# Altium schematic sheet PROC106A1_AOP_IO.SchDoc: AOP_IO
size 431 x 279 mm; Date: Not shown in title block; ApprovedBy: Not shown in title block; CheckedBy: Not shown in title block; Author: Not shown in title block; CompanyName: Not shown in title block; DrawnBy: Antony/Anand Ram; Engineer: Not shown in title block; Organization: Not shown in title block; Address1: Not shown in title block; Address2: Not shown in title block; Address3: Not shown in title block; Address4: Not shown in title block; DocumentNumber: 3; Revision: Use project parameter SCH_Rev; SheetNumber: 3; SheetTotal: 12; PageSetup: Record=PageOptions¦CenterHorizontal=True¦CenterVertical=True¦PrintScale=1.00¦XCorrection=1.00¦YCorrection=1.00¦PrintKind=0¦BorderSize=5000000¦LeftOffset=0¦BottomOffset=0¦Orientation=2¦PaperLength=1000¦PaperWidth=1000¦Scale=100¦PaperSource=15¦PrintQuality=600¦MediaType=1¦DitherType=10¦PaperKind=Letter¦PrintScaleMode=1
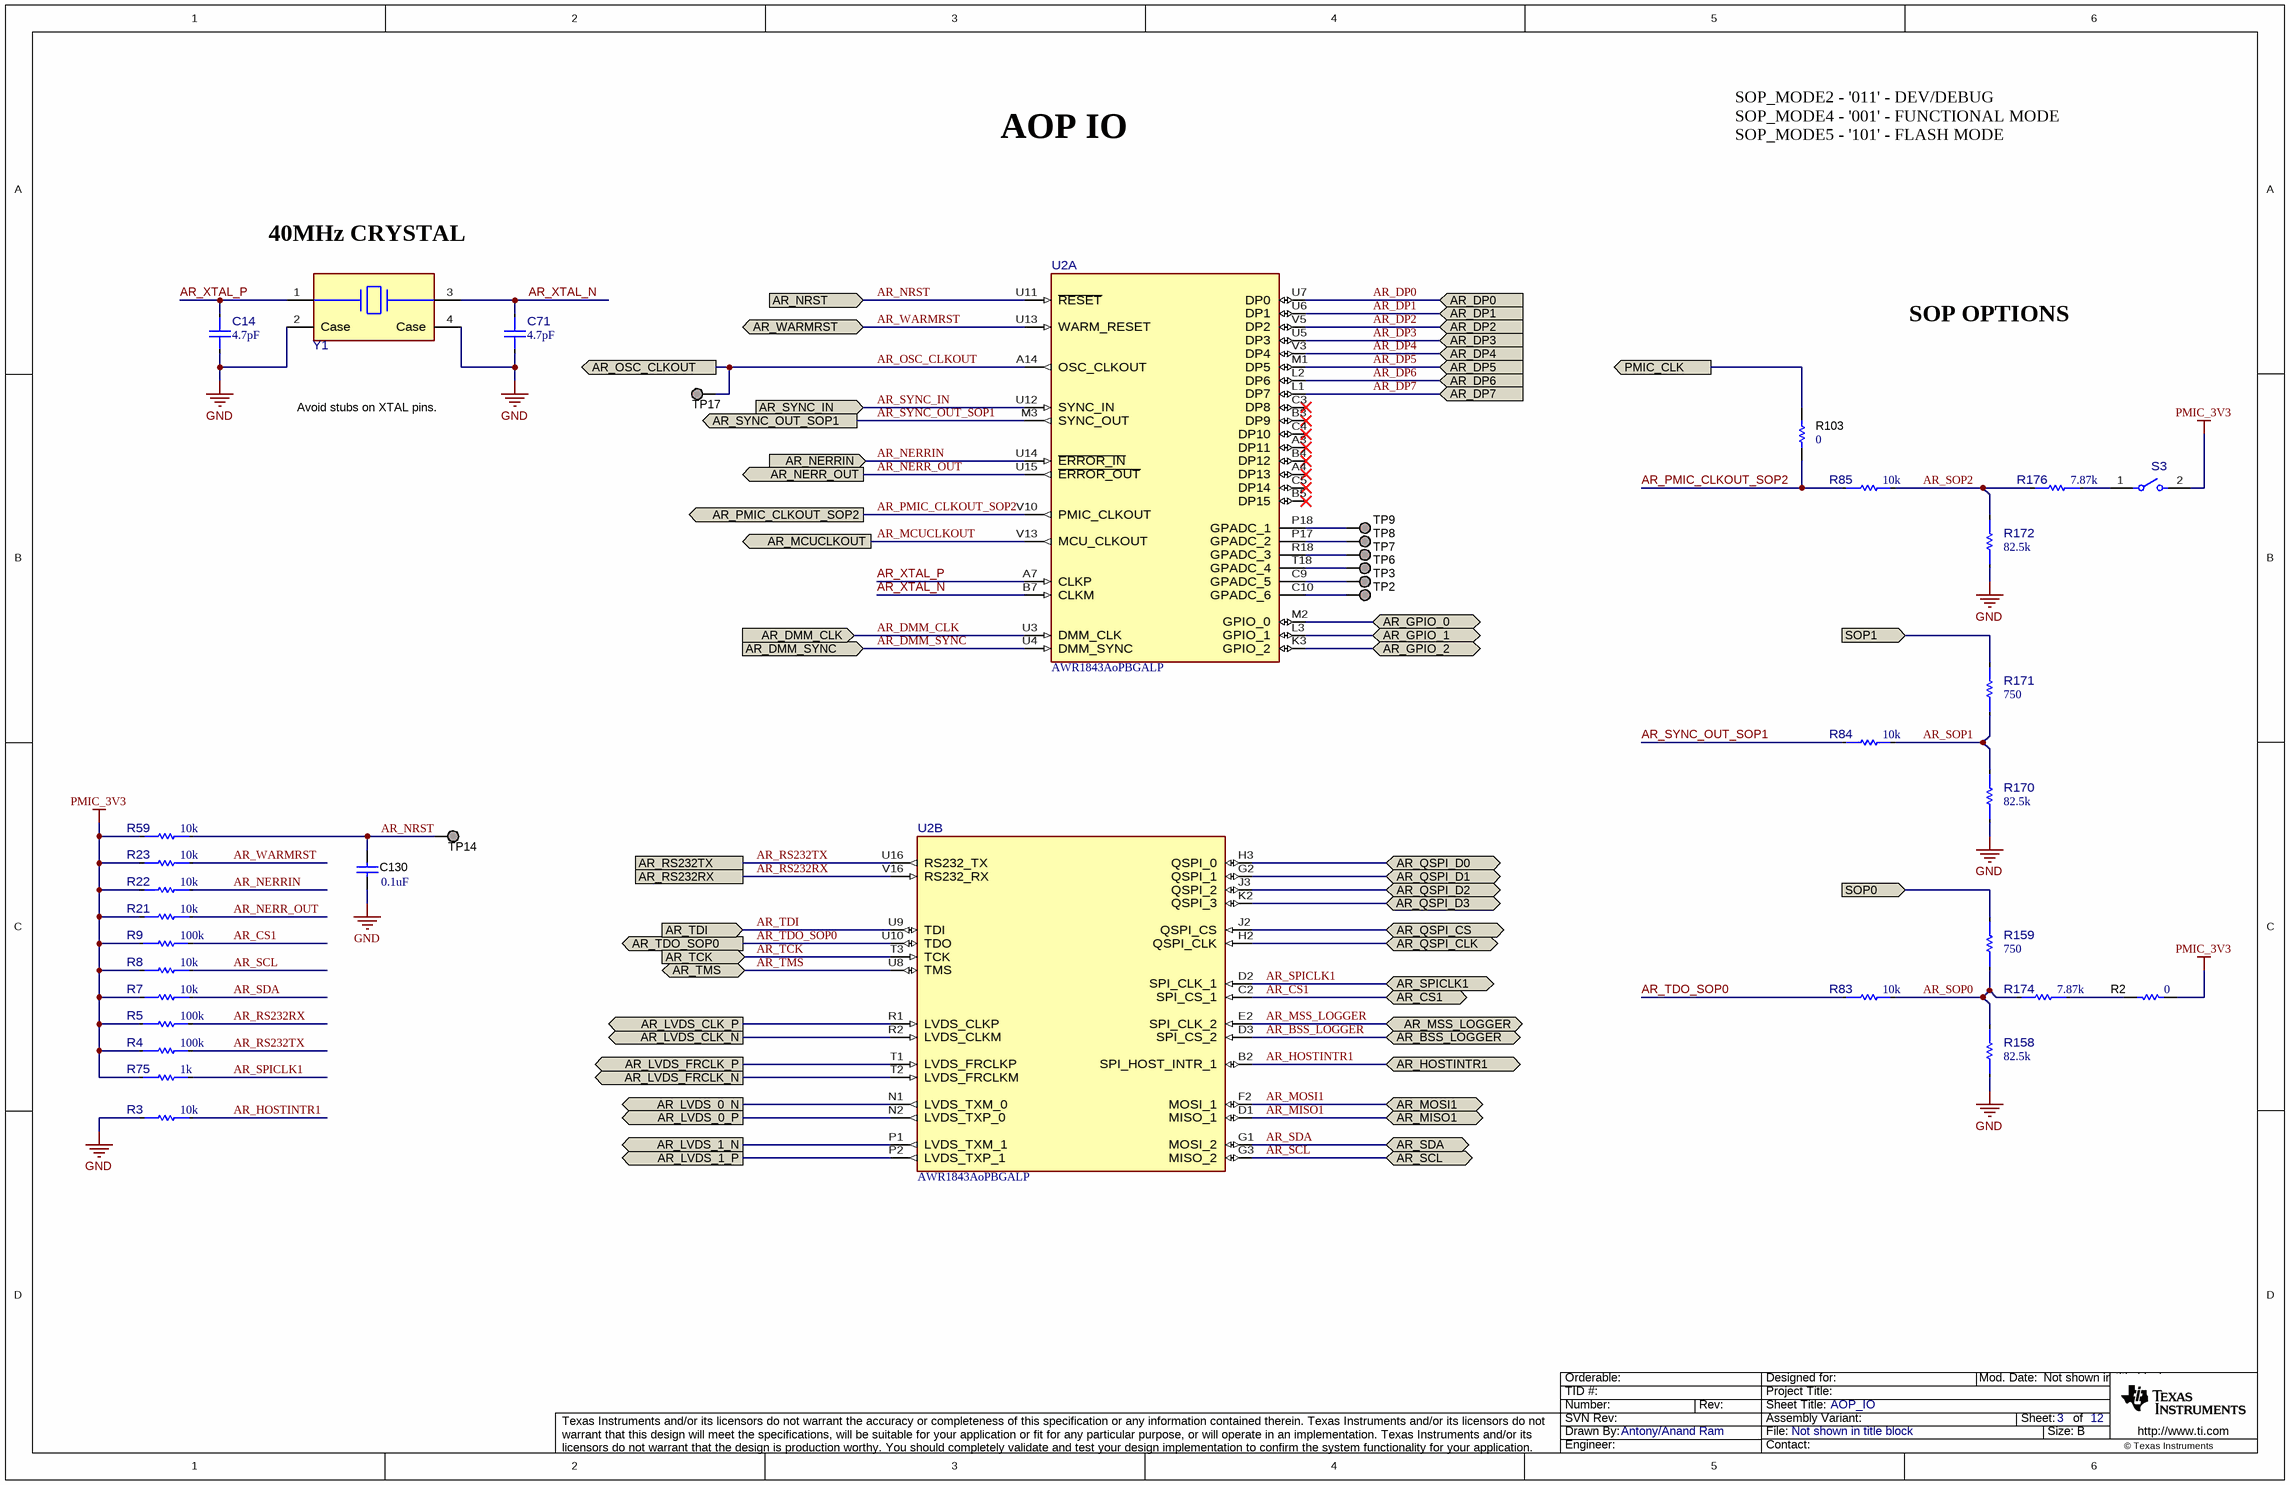
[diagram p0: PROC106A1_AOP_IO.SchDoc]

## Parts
C14  ValueDisplayed: 4.7pF  [FP-CGA1A2C0G1H4R7C030BA_0201-IPC_C]  (hidden comment: CGA1A2C0G1H4R7C030BA)
C71  ValueDisplayed: 4.7pF  [FP-CGA1A2C0G1H4R7C030BA_0201-IPC_C]  (hidden comment: CGA1A2C0G1H4R7C030BA)
C130  ValueDisplayed: 0.1uF  [0402L]  (hidden comment: GCM155R71C104KA55D)
R2  ValueDisplayed: 0  [0201L]  (hidden comment: ERJ-1GN0R00C)
R3  value 10k  [FP-ERA-1AEB103C_0201-IPC_C]  (hidden comment: ERA-1AEB103C)
R4  value 100k  [FP-ERJ-1GNF1003C_0201-IPC_C]  (hidden comment: ERJ-1GNF1003C)
R5  value 100k  [FP-ERJ-1GNF1003C_0201-IPC_C]  (hidden comment: ERJ-1GNF1003C)
R7  value 10k  [FP-ERA-1AEB103C_0201-IPC_C]  (hidden comment: ERA-1AEB103C)
R8  value 10k  [FP-ERA-1AEB103C_0201-IPC_C]  (hidden comment: ERA-1AEB103C)
R9  value 100k  [FP-ERJ-1GNF1003C_0201-IPC_C]  (hidden comment: ERJ-1GNF1003C)
R21  value 10k  [FP-ERA-1AEB103C_0201-IPC_C]  (hidden comment: ERA-1AEB103C)
R22  value 10k  [FP-ERA-1AEB103C_0201-IPC_C]  (hidden comment: ERA-1AEB103C)
R23  value 10k  [FP-ERA-1AEB103C_0201-IPC_C]  (hidden comment: ERA-1AEB103C)
R59  value 10k  [FP-ERA-1AEB103C_0201-IPC_C]  (hidden comment: ERA-1AEB103C)
R75  value 1k  [FP-ERJ-1GNJ102C_0201-IPC_C]  (hidden comment: ERJ-1GNJ102C)
R83  value 10k  [FP-ERA-1AEB103C_0201-IPC_C]  (hidden comment: ERA-1AEB103C)
R84  value 10k  [FP-ERA-1AEB103C_0201-IPC_C]  (hidden comment: ERA-1AEB103C)
R85  value 10k  [FP-ERA-1AEB103C_0201-IPC_C]  (hidden comment: ERA-1AEB103C)
R103  ValueDisplayed: 0  [0201L]  (hidden comment: ERJ-1GN0R00C)
R158  value 82.5k  [FP-ERJ-1GNF8252C_0201-IPC_C]  (hidden comment: ERJ-1GNF8252C)
R159  value 750  [FP-ERJ-1GNJ751C_0201-IPC_C]  (hidden comment: ERJ-1GNJ751C)
R170  value 82.5k  [FP-ERJ-1GNF8252C_0201-IPC_C]  (hidden comment: ERJ-1GNF8252C)
R171  value 750  [FP-ERJ-1GNJ751C_0201-IPC_C]  (hidden comment: ERJ-1GNJ751C)
R172  value 82.5k  [FP-ERJ-1GNF8252C_0201-IPC_C]  (hidden comment: ERJ-1GNF8252C)
R174  value 7.87k  [FP-ERJ-1GNF7871C_0201-IPC_C]  (hidden comment: ERJ-1GNF7871C)
R176  value 7.87k  [FP-ERJ-1GNF7871C_0201-IPC_C]  (hidden comment: ERJ-1GNF7871C)
S3  CHS-01TA  [FP-CHS-01TA_SMT_SW_5MM4_2MM5-MFG]  (value not drawn)
TP2  TESTPOINT  [TP_25MIL-SMT]  (value not drawn)  (no BOM)
TP3  TESTPOINT  [TP_25MIL-SMT]  (value not drawn)  (no BOM)
TP6  TESTPOINT  [TP_25MIL-SMT]  (value not drawn)  (no BOM)
TP7  TESTPOINT  [TP_25MIL-SMT]  (value not drawn)  (no BOM)
TP8  TESTPOINT  [TP_25MIL-SMT]  (value not drawn)  (no BOM)
TP9  TESTPOINT  [TP_25MIL-SMT]  (value not drawn)  (no BOM)
TP14  TESTPOINT  [TP_25MIL-SMT]  (value not drawn)  (no BOM)
TP17  TESTPOINT  [TP_25MIL-SMT]  (value not drawn)  (no BOM)
U2  AWR1843AoPBGALP  [ALP0180A-MFG]  (parts A,B of 5)
Y1  FW4000044Q  [FP-FW4000044Q_4-SMD-2.0x1.6mm-MFG]  (value not drawn)

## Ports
AR_BSS_LOGGER (bidir), AR_CS1 (bidir), AR_DMM_CLK (in), AR_DMM_SYNC (in), AR_DP0 (in), AR_DP1 (in), AR_DP2 (in), AR_DP3 (in), AR_DP4 (in), AR_DP5 (in), AR_DP6 (in), AR_DP7 (in), AR_GPIO_0 (bidir), AR_GPIO_1 (bidir), AR_GPIO_2 (bidir), AR_HOSTINTR1 (bidir), AR_LVDS_0_N (out), AR_LVDS_0_P (out), AR_LVDS_1_N (out), AR_LVDS_1_P (out), AR_LVDS_CLK_N (out), AR_LVDS_CLK_P (out), AR_LVDS_FRCLK_N (out), AR_LVDS_FRCLK_P (out), AR_MCUCLKOUT (out), AR_MISO1 (bidir), AR_MOSI1 (bidir), AR_MSS_LOGGER (bidir), AR_NERR_OUT (out), AR_NERRIN (in), AR_NRST (in), AR_OSC_CLKOUT (out), AR_PMIC_CLKOUT_SOP2 (out), AR_QSPI_CLK (bidir), AR_QSPI_CS (bidir), AR_QSPI_D0 (bidir), AR_QSPI_D1 (bidir), AR_QSPI_D2 (bidir), AR_QSPI_D3 (bidir), AR_RS232RX, AR_RS232TX, AR_SCL (bidir), AR_SDA (bidir), AR_SPICLK1 (bidir), AR_SYNC_IN (in), AR_SYNC_OUT_SOP1 (out), AR_TCK (in), AR_TDI (in), AR_TDO_SOP0 (out), AR_TMS (bidir), AR_WARMRST (bidir), PMIC_CLK (out), SOP0 (in), SOP1 (in)

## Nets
GND: C14.2 C71.2 C130.1 R3.2 R158.1 R170.1 R172.1 Y1.2(Case) Y1.4(Case)
PMIC_3V3: R2.2 R4.1 R5.1 R7.2 R8.2 R9.1 R21.2 R22.2 R23.2 R59.2 R75.1 S3.2
AR_BSS_LOGGER: U2.D3(SPI_CS_2) ; port AR_BSS_LOGGER
AR_CS1: R9.2 U2.C2(SPI_CS_1) ; port AR_CS1
AR_DMM_CLK: U2.U3(DMM_CLK) ; port AR_DMM_CLK
AR_DMM_SYNC: U2.U4(DMM_SYNC) ; port AR_DMM_SYNC
AR_DP0: U2.U7(DP0) ; port AR_DP0
AR_DP1: U2.U6(DP1) ; port AR_DP1
AR_DP2: U2.V5(DP2) ; port AR_DP2
AR_DP3: U2.U5(DP3) ; port AR_DP3
AR_DP4: U2.V3(DP4) ; port AR_DP4
AR_DP5: U2.M1(DP5) ; port AR_DP5
AR_DP6: U2.L2(DP6) ; port AR_DP6
AR_DP7: U2.L1(DP7) ; port AR_DP7
AR_GPIO_0: U2.M2(GPIO_0) ; port AR_GPIO_0
AR_GPIO_1: U2.L3(GPIO_1) ; port AR_GPIO_1
AR_GPIO_2: U2.K3(GPIO_2) ; port AR_GPIO_2
AR_HOSTINTR1: R3.1 U2.B2(SPI_HOST_INTR_1) ; port AR_HOSTINTR1
AR_LVDS_0_N: U2.N1(LVDS_TXM_0) ; port AR_LVDS_0_N
AR_LVDS_0_P: U2.N2(LVDS_TXP_0) ; port AR_LVDS_0_P
AR_LVDS_1_N: U2.P1(LVDS_TXM_1) ; port AR_LVDS_1_N
AR_LVDS_1_P: U2.P2(LVDS_TXP_1) ; port AR_LVDS_1_P
AR_LVDS_CLK_N: U2.R2(LVDS_CLKM) ; port AR_LVDS_CLK_N
AR_LVDS_CLK_P: U2.R1(LVDS_CLKP) ; port AR_LVDS_CLK_P
AR_LVDS_FRCLK_N: U2.T2(LVDS_FRCLKM) ; port AR_LVDS_FRCLK_N
AR_LVDS_FRCLK_P: U2.T1(LVDS_FRCLKP) ; port AR_LVDS_FRCLK_P
AR_MCUCLKOUT: U2.V13(MCU_CLKOUT) ; port AR_MCUCLKOUT
AR_MISO1: U2.D1(MISO_1) ; port AR_MISO1
AR_MOSI1: U2.F2(MOSI_1) ; port AR_MOSI1
AR_MSS_LOGGER: U2.E2(SPI_CLK_2) ; port AR_MSS_LOGGER
AR_NERR_OUT: R21.1 U2.U15(~{ERROR_OUT}) ; port AR_NERR_OUT
AR_NERRIN: R22.1 U2.U14(~{ERROR_IN}) ; port AR_NERRIN
AR_NRST: C130.2 R59.1 TP14.1 U2.U11(~{RESET}) ; port AR_NRST
AR_OSC_CLKOUT: TP17.1 U2.A14(OSC_CLKOUT) ; port AR_OSC_CLKOUT
AR_PMIC_CLKOUT_SOP2: R85.1 R103.1 U2.V10(PMIC_CLKOUT) ; port AR_PMIC_CLKOUT_SOP2
AR_QSPI_CLK: U2.H2(QSPI_CLK) ; port AR_QSPI_CLK
AR_QSPI_CS: U2.J2(QSPI_CS) ; port AR_QSPI_CS
AR_QSPI_D0: U2.H3(QSPI_0) ; port AR_QSPI_D0
AR_QSPI_D1: U2.G2(QSPI_1) ; port AR_QSPI_D1
AR_QSPI_D2: U2.J3(QSPI_2) ; port AR_QSPI_D2
AR_QSPI_D3: U2.K2(QSPI_3) ; port AR_QSPI_D3
AR_RS232RX: R5.2 U2.V16(RS232_RX) ; port AR_RS232RX
AR_RS232TX: R4.2 U2.U16(RS232_TX) ; port AR_RS232TX
AR_SCL: R8.1 U2.G3(MISO_2) ; port AR_SCL
AR_SDA: R7.1 U2.G1(MOSI_2) ; port AR_SDA
AR_SOP0: R83.2 R158.2 R159.1 R174.2
AR_SOP1: R84.2 R170.2 R171.1
AR_SOP2: R85.2 R172.2 R176.2
AR_SPICLK1: R75.2 U2.D2(SPI_CLK_1) ; port AR_SPICLK1
AR_SYNC_IN: U2.U12(SYNC_IN) ; port AR_SYNC_IN
AR_SYNC_OUT_SOP1: R84.1 U2.M3(SYNC_OUT) ; port AR_SYNC_OUT_SOP1
AR_TCK: U2.T3(TCK) ; port AR_TCK
AR_TDI: U2.U9(TDI) ; port AR_TDI
AR_TDO_SOP0: R83.1 U2.U10(TDO) ; port AR_TDO_SOP0
AR_TMS: U2.U8(TMS) ; port AR_TMS
AR_WARMRST: R23.1 U2.U13(WARM_RESET) ; port AR_WARMRST
AR_XTAL_N: C71.1 U2.B7(CLKM) Y1.3(2_Xtal)
AR_XTAL_P: C14.1 U2.A7(CLKP) Y1.1(1_Xtal)
PMIC_CLK: R103.2 ; port PMIC_CLK
SOP0: R159.2 ; port SOP0
SOP1: R171.2 ; port SOP1
NetR2_1: R2.1 R174.1
NetR176_1: R176.1 S3.1
NetTP2_1: TP2.1 U2.C10(GPADC_6)
NetTP3_1: TP3.1 U2.C9(GPADC_5)
NetTP6_1: TP6.1 U2.T18(GPADC_4)
NetTP7_1: TP7.1 U2.R18(GPADC_3)
NetTP8_1: TP8.1 U2.P17(GPADC_2)
NetTP9_1: TP9.1 U2.P18(GPADC_1)

Not connected (* = marked no-connect by the designer): U2 A3(DP11)* A4(DP13)* B3(DP9)* B4(DP12)* B5(DP15)* C3(DP8)* C4(DP10)* C5(DP14)*

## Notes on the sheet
- AOP IO
- SOP_MODE2 - '011' - DEV/DEBUG
  SOP_MODE4 - '001' - FUNCTIONAL MODE
  SOP_MODE5 - '101' - FLASH MODE
- 40MHz CRYSTAL
- SOP OPTIONS
- Avoid stubs on XTAL pins.

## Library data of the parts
C14 C71 = CMP-0090493-1: Cap Ceramic 4.7pF 50V C0G 0.25pF Pad SMD 0201 125°C Automotive T/R; Manufacturer: TDK; AEC Grade: Grade 1; AEC Qualified: Yes; SizeZ_mm: 0.4mm; TempCo: 30ppm/°C
C130 = CMP-0006351-2: CAP, CERM, 0.1 uF, 16 V, +/- 10%, X7R, 0402; Manufacturer: MuRata; Cap_F: 100nF; SizeZ_mm: 0.6; VDC_V: 16V; AEC Category: Q200; Cap_Case: 0402; Polarized: N; SizeArea_mm2: 0.5; SizeAreaWB_mm2: 3; SizeX_mm: 1; TaMax_C: 125°C; TaMin_C: -55°C; U/M: EA; Value1: Unknown; Value: 0.1uF
R2 R103 = CMP-0065361-1: RES, 0, 5%, .05 W, AEC-Q200 Grade 0, 0201; Manufacturer: Panasonic; AEC Qualified: Y; Power_W: 50mW; SizeZ_mm: 0.26; TempCo: ppm/C; AEC Category: Q200; EIA_Code: E24; Green_Lifecycle: Not Set; Green_REACh: Incomplete; SizeArea_mm2: 0.18; SizeX_mm: 0.6; SizeY_mm: 0.3; U/M: EA; Value2: .05W; Value: 0; Value_Code: 0000
R3 R7 R8 R21-R23 R59 R83-R85 = CMP-0090084-1: RES SMD 10K OHM 0.1% 1/20W 0201; Manufacturer: Panasonic; AEC Qualified: No; Power_W: 50mW; SizeZ_mm: 0.26mm; TempCo: 25ppm/°C; VDC_V: 25V
R4 R5 R9 = CMP-0090298-1: 100 kOhms ±1% 0.05W, 1/20W Chip Resistor 0201 (0603 Metric) Automotive AEC-Q200 Thick Film; Manufacturer: Panasonic Electronic Components; AEC Grade: Grade 1; AEC Qualified: Yes; Power_W: 50mW; SizeZ_mm: 0.26mm; TempCo: 200ppm/°C; VDC_V: 25V
R75 = CMP-0090500-1: 1 kOhms ±5% 0.05W, 1/20W Chip Resistor 0201 (0603 Metric) Automotive AEC-Q200 Thick Film; Manufacturer: Panasonic Electronic Components; AEC Grade: Grade 1; AEC Qualified: Yes; Power_W: 50mW; SizeZ_mm: 0.26mm; TempCo: 200ppm/°C; VDC_V: 25V
R158 R170 R172 = CMP-0090499-1: Res Thick Film 0201 82.5K Ohm 1% 1/20W ±200ppm/°C Molded SMD SMD T/R; Manufacturer: Panasonic; AEC Grade: Grade 1; AEC Qualified: Yes; Power_W: 50mW; SizeZ_mm: 0.26mm; VDC_V: 25V
R159 R171 = CMP-0090503-1: Res Thick Film 0201 750 Ohm 5% 0.05W(1/20W) ±200ppm/C Pad SMD Automotive T/R; Manufacturer: Panasonic Electronic Components; AEC Grade: Grade 1; AEC Qualified: Yes; Power_W: 50mW; SizeZ_mm: 0.26mm; TempCo: 200ppm/°C; VDC_V: 25V
R174 R176 = CMP-0090498-1: Res Thick Film 0201 7.87K Ohm 1% 1/20W ±200ppm/°C Molded SMD SMD T/R; Manufacturer: Panasonic; AEC Grade: Grade 1; AEC Qualified: Yes; Power_W: 50mW; SizeZ_mm: 0.26mm; VDC_V: 25V
S3 = CMP-0087181-1: SWITCH SLIDE DIP SPST 100MA 6V; Manufacturer: Nidec Copal Electronics; PositionCount: 1; SizeZ_mm: 2.5mm; Symbol Name: SYM-CHS-01TA
TP2 TP3 TP6-TP9 TP14 TP17 = CMP-0078143-3: TEST POINT.  No entry in BOM.
U2 = CMP-0090288-2: Manufacturer: Texas Instruments; Standoff Height: 0.31mm; SizeZ_mm: 0.965mm; AEC Category: Q200; CompType: IC
Y1 = CMP-0090505-1: 40MHz ±10ppm Crystal 8pF 50 Ohms 4-SMD, No Lead; Manufacturer: Diodes; AEC Qualified: Yes; Frequency Stability: 50ppm; SizeZ_mm: 0.55mm; AEC Grade: Grade 1; Esr: 50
